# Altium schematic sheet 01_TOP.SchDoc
size 420 x 297 mm
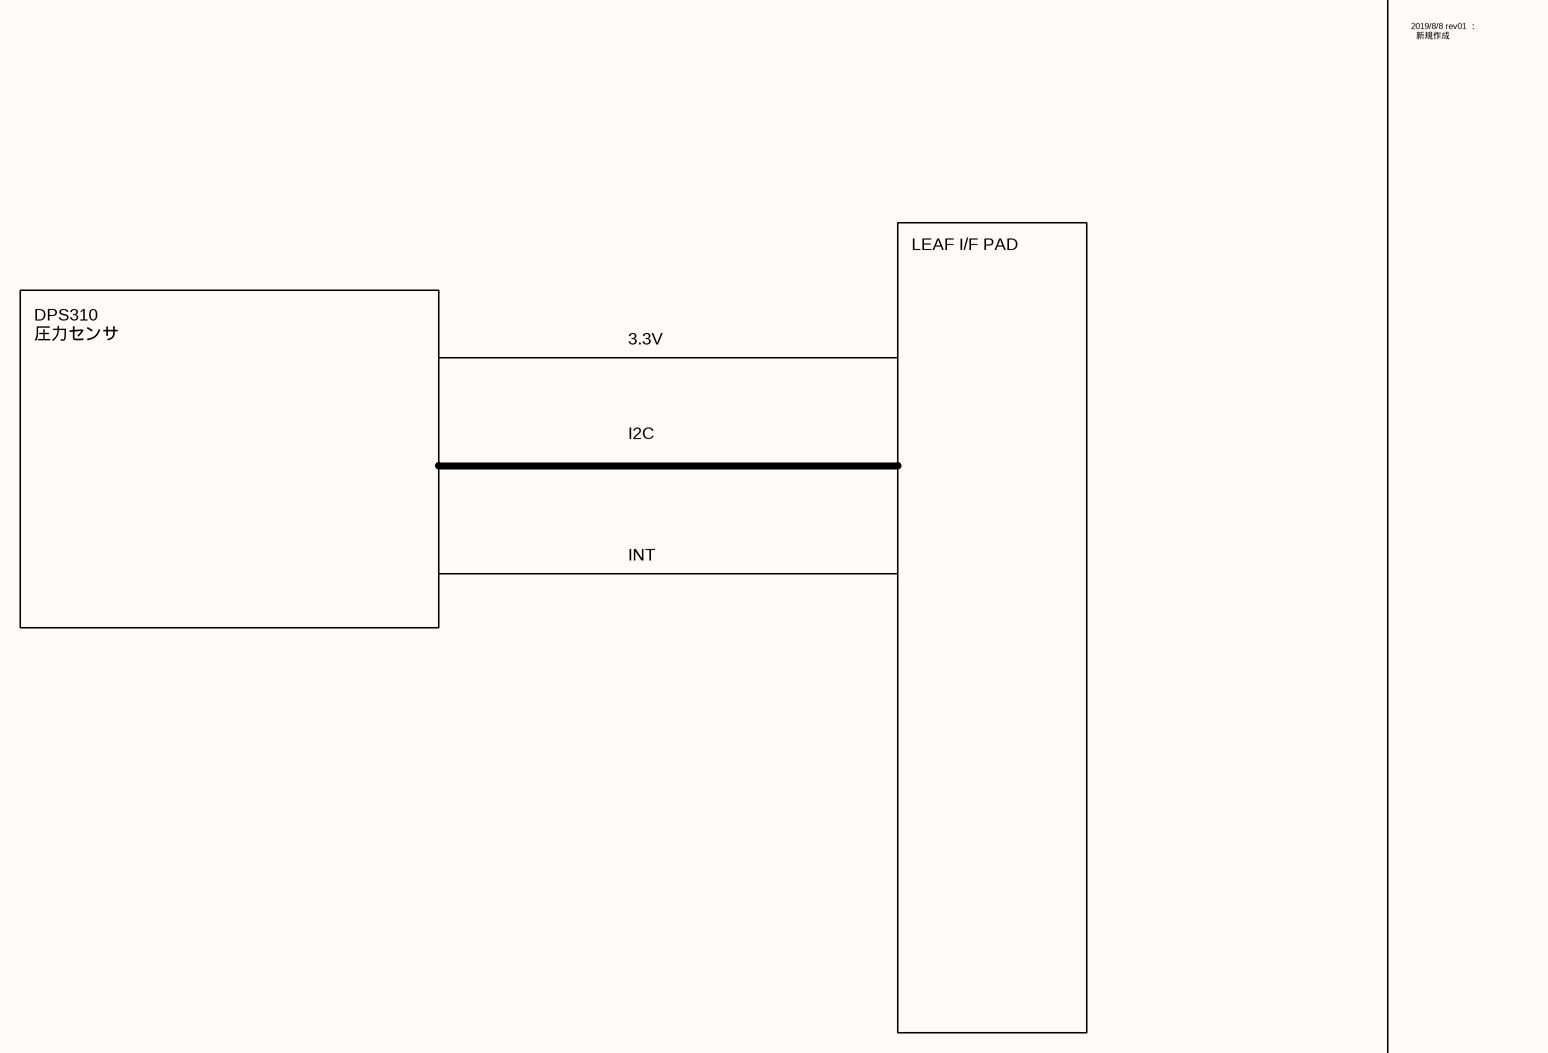
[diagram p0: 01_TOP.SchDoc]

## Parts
*  Confidential: NEXTY Electronics Corporation Confidential  RevCode: 01  Page Size: A3  Page Number: 2  Page Count: 3  Project Name: Trillion Node  Project ID: REF051  Sheet Name: TOP  Schematic No.: REF051-SCH013  (hidden comment: TitleBlock_NEXTY-Ele)  (graphical)

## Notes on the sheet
- 2019/8/8 rev01 ：
  新規作成
- LEAF I/F PAD
- DPS310
  圧力センサ
- 3.3V
- I2C
- INT

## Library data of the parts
* = TitleBlock_NEXTY-Ele: Sample: 例; Histry_First: 完成___Rev1.0; Date2: △△△△年△△月△△日; RevChange: Rev1.0 → 1.1; Histry: B-3_Net___PG0 → PG1; date_drawn: (     /    /   )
